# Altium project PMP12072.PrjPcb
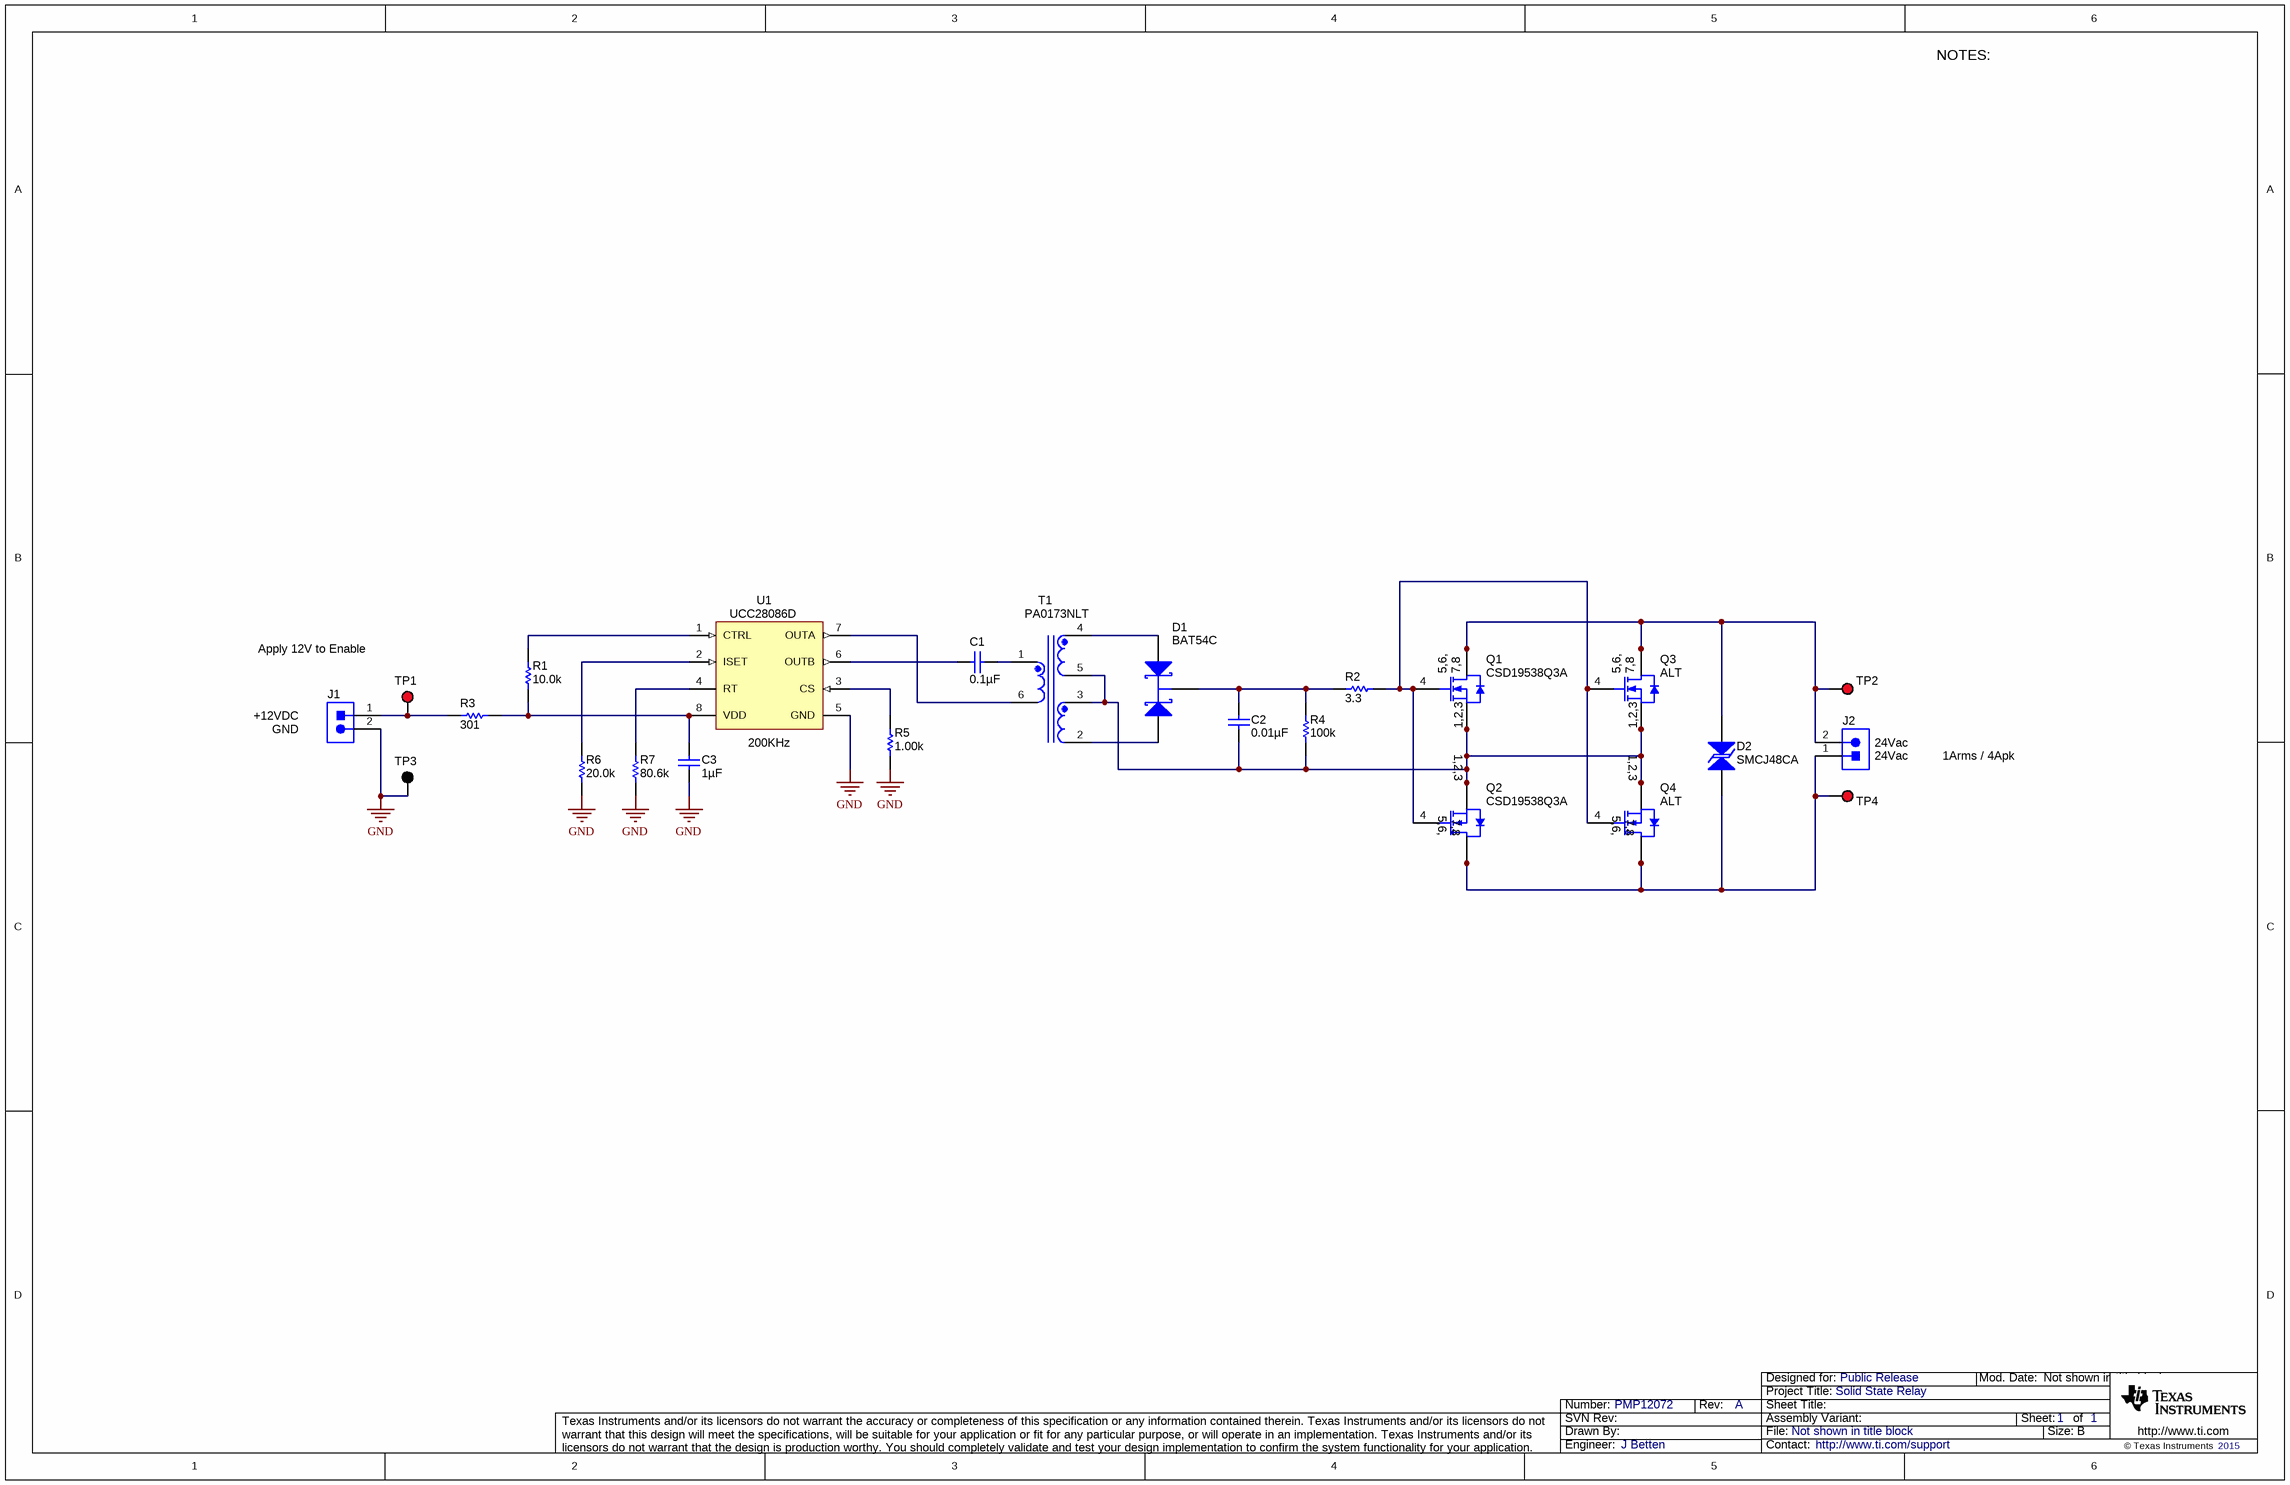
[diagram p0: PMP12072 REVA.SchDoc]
TechSupport: http://www.ti.com/support; SCH_Rev: A; PRJ_Title: Solid State Relay; PRJ_Number: PMP12072; PRJ_Engineer: J Betten; PRJ_Customer: Public Release; PCB_Rev: A; PCB_Layout: J Betten; CopyrightYear: 2015
1 sheet, 24 parts. Net scope: global (net labels, ports and power ports of the same name join across sheets).
Board file: PMP12072 REVA.PcbDoc

## Sheet PMP12072 REVA.SchDoc
size 431 x 279 mm; Date: Not shown in title block; ApprovedBy: Not shown in title block; CheckedBy: Not shown in title block; Author: Not shown in title block; CompanyName: Not shown in title block; Engineer: Not shown in title block; Organization: Not shown in title block; Address1: Not shown in title block; Address2: Not shown in title block; Address3: Not shown in title block; Address4: Not shown in title block; DocumentNumber: 1; Revision: Use project parameter SCH_Rev; SheetNumber: 1; SheetTotal: 1; PageSetup: Record=PageOptions¦CenterHorizontal=True¦CenterVertical=True¦PrintScale=1.00¦XCorrection=1.00¦YCorrection=1.00¦PrintKind=0¦BorderSize=5000000¦LeftOffset=0¦BottomOffset=0¦Orientation=2¦PaperLength=1000¦PaperWidth=1000¦Scale=100¦PaperSource=15¦PrintQuality=600¦MediaType=1¦DitherType=10¦PaperKind=Letter¦PrintScaleMode=1

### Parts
C1  ValueDisplayed: 0.1µF  [0603]  (hidden comment: C1608X7R1H104K)
C2  ValueDisplayed: 0.01µF  [0603]  (hidden comment: C1608X7R1H103K)
C3  ValueDisplayed: 1µF  [0603]  (hidden comment: C1608X5R1C105K)
D1  BAT54C  [SOT-23]
D2  SMCJ48CA  [SMC]
J1  ED555/2DS  [TERM_BLK_ED555-2DS]  (value not drawn)
J2  ED555/2DS  [TERM_BLK_ED555-2DS]  (value not drawn)
Q1  CSD19538Q3A  [DNH0008A]
Q2  CSD19538Q3A  [DNH0008A]
Q3  ALT  [TRANS_NexFET_Q5A]
Q4  ALT  [TRANS_NexFET_Q5A]
R1  ValueDisplayed: 10.0k  [0603]  (hidden comment: CRCW060310K0FKEA)
R2  value 3.3  [0603]  (hidden comment: CRCW06033R30JNEA)
R3  value 301  [0805_HV]  (hidden comment: CRCW0805301RFKEA)
R4  value 100k  [0603]  (hidden comment: CRCW0603100KFKEA)
R5  ValueDisplayed: 1.00k  [0603]  (hidden comment: CRCW06031K00FKEA)
R6  ValueDisplayed: 20.0k  [0603]  (hidden comment: CRCW060320K0FKEA)
R7  ValueDisplayed: 80.6k  [0603]  (hidden comment: CRCW060380K6FKEA)
T1  PA0173NLT  [PULSE_PA0173]
TP1  5000  [Keystone5000]  (value not drawn)
TP2  5000  [Keystone5000]  (value not drawn)
TP3  5001  [Keystone5001]  (value not drawn)
TP4  5000  [Keystone5000]  (value not drawn)
U1  UCC28086D  [D0008A_N]

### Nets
GND: C3.1 J1.2 R5.2 R6.2 R7.2 TP3.1 U1.5(GND)
NetC1_1: C1.1 U1.6(OUTB)
NetC1_2: C1.2 T1.1
NetC2_1: C2.1 D1.3(K) R2.2 R4.2
NetC2_2: C2.2 Q1.1(S) Q1.2(S) Q1.3(S) Q2.1(S) Q2.2(S) Q2.3(S) Q3.1(S) Q3.2(S) Q3.3(S) Q4.1(S) Q4.2(S) Q4.3(S) R4.1 T1.3 T1.5
NetC3_2: C3.2 R1.2 R3.2 U1.8(VDD)
NetD1_1: D1.1(A1) T1.4
NetD1_2: D1.2(A2) T1.2
NetD2_1: D2.1 J2.2 Q1.5(D) Q1.6(D) Q1.7(D) Q1.8(D) Q1.9(D) Q3.5(D) Q3.6(D) Q3.7(D) Q3.8(D) Q3.9(D) TP2.1
NetD2_2: D2.2 J2.1 Q2.5(D) Q2.6(D) Q2.7(D) Q2.8(D) Q2.9(D) Q4.5(D) Q4.6(D) Q4.7(D) Q4.8(D) Q4.9(D) TP4.1
NetJ1_1: J1.1 R3.1 TP1.1
NetQ1_4: Q1.4(G) Q2.4(G) Q3.4(G) Q4.4(G) R2.1
NetR1_1: R1.1 U1.1(CTRL)
NetR5_1: R5.1 U1.3(CS)
NetR6_1: R6.1 U1.2(ISET)
NetR7_1: R7.1 U1.4(RT)
NetT1_6: T1.6 U1.7(OUTA)

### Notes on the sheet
- NOTES:
- Apply 12V to Enable
- GND
- +12VDC
- (near U1) 200KHz
- (near J2) 24Vac
- 24Vac
- 1Arms / 4Apk

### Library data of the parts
C1 = C1608X7R1H104K: CAP, CERM, 0.1uF, 50V, +/-10%, X7R, 0603; Manufacturer: TDK; Polarized: N; CompType: Capacitor; U/M: EA; Cap_F: 0.0000001; Tolerance_%: 10; ESR_Ohm: 0.017; Value1: 0.017 ohm; VDC_V: 50; TaMin_C: -55; TaMax_C: 125
C2 = C1608X7R1H103K: CAP, CERM, 0.01uF, 50V, +/-10%, X7R, 0603; Manufacturer: TDK; Polarized: N; CompType: Capacitor; U/M: EA; Cap_F: 0.00000001; Tolerance_%: 10; ESR_Ohm: 0.0539; Value1: 0.0539 ohm; VDC_V: 50; TaMin_C: -55; TaMax_C: 125
C3 = C1608X5R1C105K: CAP, CERM, 1uF, 16V, +/-10%, X5R, 0603; Manufacturer: TDK; Polarized: N; CompType: Capacitor; U/M: EA; Cap_F: 0.000001; Tolerance_%: 10; ESR_Ohm: 0.0057; Value1: 0.0057 ohm; VDC_V: 16; TaMin_C: -55; TaMax_C: 85
D1 = BAT54C-7-F: Diode, Schottky, 30V, 0.2A, SOT-23; Manufacturer: Diodes Inc.; U/M: EA; Vf_V: 0.65; Value2: 0.65V; Io_A: 0.2; Vr_V: 30; TJmax_C: 125
D2 = SMCJ33CA: Diode, TVS, Bi, 48V, 1500W, SMC; Manufacturer: Bourns; U/M: EA; Power_W: 1500; Vr_V: 48
J1 J2 = ED555/2DS: Terminal Block, 6A, 3.5mm Pitch, 2-Pos, TH; Manufacturer: On-Shore Technology; SymbolCreator: a0412235; CompType: Connector; U/M: EA
Q1 Q2 = CSD19538Q3A: MOSFET, N-CH, 100 V, 5 A, DNH0008A; Manufacturer: Texas Instruments; Alternate Manufacturer: None; U/M: EA; ChType: N; Value: 100V; VdsMax_V: 100; Value1: ? ohm; Value2: 7.2 nC; QgTyp_nC: 7.2; Vgs_V: 20; IdsMax_A: 5; AEC Category: Q101
Q3 Q4 = CSD19534Q5A: MOSFET, SON 5x6mm; Manufacturer: Texas Instruments; Alternate Manufacturer: None; U/M: EA; ChType: N; IdsMax_A: 10; AEC Category: Q101
R1 = CRCW060310K0FKEA: RES, 10.0 k, 1%, 0.1 W, 0603; Manufacturer: Vishay-Dale; CompType: Resistor; Value: 10.0k; Res_ohm: 10000; Value_Code: 10k0; Tolerance_%: 1; Power_W: 0.1; Value2: 0.1W; VDC_V: 75; TempCo: 100 ppm/C; EIA_Code: E96; U/M: EA
R2 = CRCW06033R30JNEA: RES, 3.3 ohm, 5%, 0.1W, 0603; Manufacturer: Vishay-Dale; CompType: Resistor; Value_Code: 3R30; Tolerance_%: 5; Power_W: 0.1; VDC_V: 75; TempCo: 200 ppm/C; EIA_Code: E24; U/M: EA
R3 = CRCW0805301RFKEA: RES, 301 ohm, 1%, 0.125W, 0805; Manufacturer: Vishay-Dale; CompType: Resistor; Value_Code: 301R; Tolerance_%: 1; Power_W: 0.125; VDC_V: 150; TempCo: 100 ppm/C; EIA_Code: E96; U/M: EA
R4 = CRCW0603100KFKEA: RES, 100k ohm, 1%, 0.1W, 0603; Manufacturer: Vishay-Dale; CompType: Resistor; Res_ohm: 100000; Tolerance_%: 1; Power_W: 0.1; VDC_V: 75; TempCo: 100 ppm/C; EIA_Code: E96; U/M: EA
R5 = CRCW06031K00FKEA: RES, 1.00 k, 1%, 0.1 W, 0603; Manufacturer: Vishay-Dale; CompType: Resistor; Value: 1.00k; Res_ohm: 1000; Value_Code: 1k00; Tolerance_%: 1; Power_W: 0.1; Value2: 0.1W; VDC_V: 75; TempCo: 100 ppm/C; EIA_Code: E96; U/M: EA
R6 = CRCW060320K0FKEA: RES, 20.0 k, 1%, 0.1 W, 0603; Manufacturer: Vishay-Dale; CompType: Resistor; Value: 20.0k; Res_ohm: 20000; Value_Code: 20k0; Tolerance_%: 1; Power_W: 0.1; Value2: 0.1W; VDC_V: 75; TempCo: 100 ppm/C; EIA_Code: E96; U/M: EA
R7 = CRCW060380K6FKEA: RES, 80.6 k, 1%, 0.1 W, 0603; Manufacturer: Vishay-Dale; CompType: Resistor; Value: 80.6k; Res_ohm: 80600; Value_Code: 80k6; Tolerance_%: 1; Power_W: 0.1; Value2: 0.1W; VDC_V: 75; TempCo: 100 ppm/C; EIA_Code: E96; U/M: EA
T1 = PA0173NLT: Transformer, Gate Drive, 980uH, SMT; Manufacturer: Pulse Engineering; SymbolCreator: a0411947; DCR_Ohm: 0.62; LeakageL: 0.75uH; U/M: EA
TP1 TP2 TP4 = 5000: Test Point, Miniature, Red, TH; Manufacturer: Keystone; CompType: Test Point Loop; U/M: EA
TP3 = 5001: Test Point, Miniature, Black, TH; Manufacturer: Keystone; CompType: Test Point Loop; U/M: EA
U1 = UCC28086D: Push-Pull PWM Controller with Programmable Slope Compensation with Current Control, 50 % Duty Cycle, -40 to +85 degC, 8-pin SOIC (D), Green (RoHS & no Sb/Br); Manufacturer: Texas Instruments; Alternate Manufacturer: None; Alternate PartNumber: Equivalent; Duty Cycle(Max)(%): 50; Frequency(Max)(kHz): 1000; Rating: Catalog; Regulated Outputs(#): 2; Topology: Half-Bridge, Push-Pull; UVLO Thresholds On/Off(V): 4.3/4.1

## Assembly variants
001: not fitted FID1 FID2 FID3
